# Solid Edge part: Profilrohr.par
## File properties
Username: bmolnar
Dokumentum tartalom típus: 0
Author: bmolnar
Last saved by: bmolnar
Revision: 80
Sűrűség: 0,000 kg/m^3
Pontosság: 0,990
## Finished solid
Body 1: solid body, 115 faces, 338 edges, 224 vertices.
  Faces by surface: cylinder 59, plane 56
  Edges by curve: line 220, circle 118
Bounding box of the edges (mm): 95.500 x 95.500 x 49.000, from (-47.75, -47.75, -20) to (47.75, 47.75, 29).
Cylindrical faces by radius (mm): R0.2 x24, R0.5 x24, R1 x4, R10 x4, R13.5 x2, R40 x1
Planar faces by outward normal: +x 13, +y 14, +z 1, -x 13, -y 14, -z 1
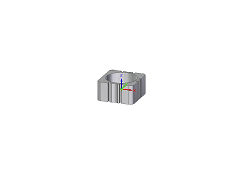
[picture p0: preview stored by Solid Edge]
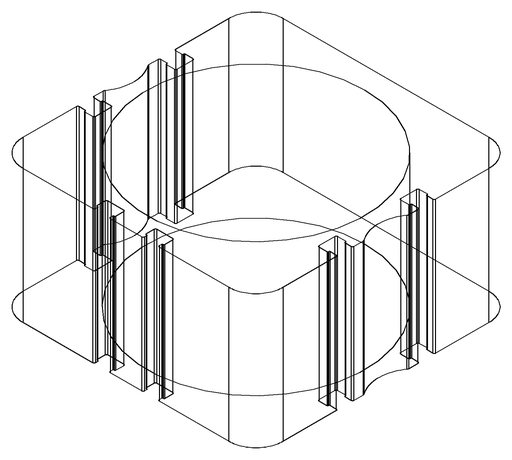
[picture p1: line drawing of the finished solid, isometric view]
